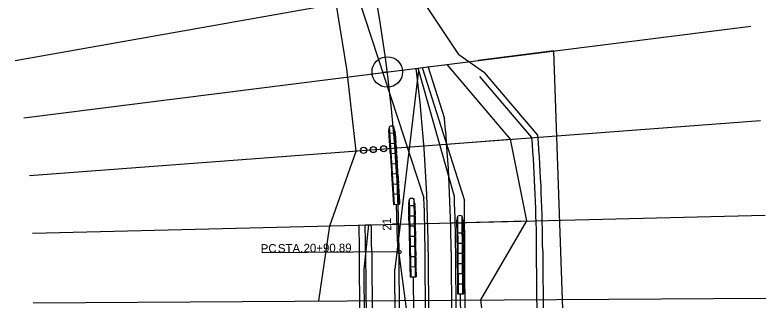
# Model space of a CAD drawing. Extents: x 2283072 to 2287933, y 586198 to 587702.
# Drawn here: x 2284307.3 to 2284553.2, y 587262.4 to 587356.1 of the extents above; entities that cross this region are included whole.
import ezdxf

# ---------------------------------------------------------------- set-up
doc = ezdxf.new("R2010")
doc.units = 0
for name, color, linetype in [('_CIVIL_CONSTRUCTION', 7, 'Continuous'), ('DR_X_Ditch', 7, 'Continuous'), ('DR_X_Headwall', 7, 'Continuous'), ('DT_X_Island', 7, 'Continuous'), ('DT_X_Terrain_Boundary', 7, 'Continuous'), ('DT_X_Void', 7, 'Continuous'), ('PV_X_EOP', 7, 'Continuous'), ('RD_P_Fence', 7, 'Continuous'), ('RS_Raster1', 7, 'Continuous'), ('RW_P_Esmt_TMP', 7, 'Continuous'), ('SV_X_Control_Cells_Found', 7, 'Continuous'), ('SV_X_Random_Point', 7, 'Continuous'), ('SV_X_Toe_of_Slope', 7, 'Continuous')]:
    doc.layers.add(name, color=color, linetype=linetype)

msp = doc.modelspace()

# ---------------------------------------------------------------- linework, layer by layer
at = {"layer": '_CIVIL_CONSTRUCTION'}
for p, q in [((2284396.97, 587431.38), (2284441.17, 587296.19)), ((2284451.16, 587296.6), (2284439.34, 587338.71)), ((2284431.58, 587294.07), (2284429.95, 587319.51)), ((2284431.28, 587319.6), (2284432.91, 587294.16)), ((2284431.71, 587318.07), (2284431.37, 587319.55)), ((2284429.72, 587317.94), (2284429.87, 587319.45)), ((2284429.75, 587317.51), (2284429.72, 587317.94)), ((2284429.92, 587317.35), (2284429.75, 587317.51)), ((2284429.77, 587317.17), (2284429.92, 587317.35)), ((2284429.96, 587314.18), (2284429.77, 587317.17)), ((2284429.92, 587317.35), (2284431.59, 587317.46)), ((2284431.59, 587317.46), (2284431.74, 587317.63)), ((2284431.76, 587317.3), (2284431.59, 587317.46)), ((2284431.71, 587318.07), (2284431.74, 587317.63)), ((2284431.76, 587317.3), (2284431.96, 587314.31)), ((2284430.14, 587314.02), (2284429.96, 587314.18)), ((2284429.98, 587313.85), (2284430.14, 587314.02)), ((2284430.17, 587310.85), (2284429.98, 587313.85)), ((2284430.14, 587314.02), (2284431.8, 587314.13)), ((2284431.8, 587314.13), (2284431.96, 587314.31)), ((2284431.98, 587313.97), (2284431.8, 587314.13)), ((2284431.98, 587313.97), (2284432.17, 587310.98)), ((2284430.35, 587310.7), (2284430.17, 587310.85)), ((2284430.19, 587310.52), (2284430.35, 587310.7)), ((2284430.19, 587310.52), (2284430.39, 587307.53)), ((2284430.35, 587310.7), (2284432.01, 587310.8)), ((2284432.01, 587310.8), (2284432.17, 587310.98)), ((2284432.19, 587310.65), (2284432.01, 587310.8)), ((2284432.19, 587310.65), (2284432.38, 587307.65)), ((2284430.56, 587307.37), (2284430.39, 587307.53)), ((2284430.41, 587307.19), (2284430.56, 587307.37)), ((2284430.56, 587307.37), (2284432.23, 587307.48)), ((2284432.23, 587307.48), (2284432.38, 587307.65)), ((2284432.4, 587307.32), (2284432.23, 587307.48)), ((2284432.4, 587307.32), (2284432.59, 587304.33)), ((2284430.41, 587307.19), (2284430.6, 587304.2)), ((2284430.78, 587304.04), (2284430.6, 587304.2)), ((2284430.62, 587303.87), (2284430.78, 587304.04)), ((2284430.62, 587303.87), (2284430.81, 587300.87)), ((2284430.78, 587304.04), (2284432.44, 587304.15)), ((2284432.44, 587304.15), (2284432.59, 587304.33)), ((2284432.62, 587303.99), (2284432.44, 587304.15)), ((2284432.62, 587303.99), (2284432.81, 587301)), ((2284430.99, 587300.72), (2284430.81, 587300.87)), ((2284430.83, 587300.54), (2284430.99, 587300.72)), ((2284430.83, 587300.54), (2284431.02, 587297.55)), ((2284430.99, 587300.72), (2284432.65, 587300.82)), ((2284432.65, 587300.82), (2284432.81, 587301)), ((2284432.83, 587300.67), (2284432.65, 587300.82)), ((2284432.83, 587300.67), (2284433.02, 587297.67)), ((2284431.2, 587297.39), (2284431.02, 587297.55)), ((2284431.05, 587297.21), (2284431.2, 587297.39)), ((2284431.2, 587297.39), (2284432.86, 587297.5)), ((2284432.86, 587297.5), (2284433.02, 587297.67)), ((2284433.04, 587297.34), (2284432.86, 587297.5)), ((2284431.05, 587297.21), (2284431.25, 587294.05)), ((2284433.04, 587297.34), (2284433.24, 587294.18)), ((2284431.25, 587294.05), (2284433.24, 587294.18)), ((2284432.57, 587282.12), (2284432.25, 587294.12)), ((2284452, 587288.65), (2284452.24, 587290.16)), ((2284452.52, 587264.72), (2284452.32, 587290.21)), ((2284453.65, 587290.22), (2284453.85, 587264.73)), ((2284454, 587288.67), (2284453.74, 587290.17)), ((2284452, 587288.22), (2284452, 587288.65)), ((2284452.17, 587288.05), (2284452, 587288.22)), ((2284452, 587287.88), (2284452.17, 587288.05)), ((2284452.03, 587284.88), (2284452, 587287.88)), ((2284452.17, 587288.05), (2284453.84, 587288.07)), ((2284453.84, 587288.07), (2284454, 587288.23)), ((2284454, 587287.9), (2284453.84, 587288.07)), ((2284454, 587288.67), (2284454, 587288.23)), ((2284454, 587287.9), (2284454.03, 587284.9)), ((2284452.2, 587284.72), (2284452.03, 587284.88)), ((2284452.03, 587284.55), (2284452.2, 587284.72)), ((2284452.05, 587281.55), (2284452.03, 587284.55)), ((2284452.2, 587284.72), (2284453.86, 587284.73)), ((2284453.86, 587284.73), (2284454.03, 587284.9)), ((2284454.03, 587284.57), (2284453.86, 587284.73)), ((2284454.03, 587284.57), (2284454.05, 587281.57)), ((2284440.46, 587222.64), (2284432.57, 587282.12)), ((2284452.22, 587281.39), (2284452.05, 587281.55)), ((2284452.06, 587281.22), (2284452.22, 587281.39)), ((2284452.06, 587281.22), (2284452.08, 587278.22)), ((2284452.22, 587281.39), (2284453.89, 587281.4)), ((2284453.89, 587281.4), (2284454.05, 587281.57)), ((2284454.06, 587281.23), (2284453.89, 587281.4)), ((2284454.06, 587281.23), (2284454.08, 587278.23)), ((2284442.67, 587114.69), (2284441.59, 587278.56)), ((2284452.67, 587114.75), (2284451.59, 587278.62)), ((2284452.25, 587278.05), (2284452.08, 587278.22)), ((2284452.08, 587277.88), (2284452.25, 587278.05)), ((2284452.08, 587277.88), (2284452.11, 587274.88)), ((2284452.25, 587278.05), (2284453.91, 587278.07)), ((2284453.91, 587278.07), (2284454.08, 587278.23)), ((2284454.08, 587277.9), (2284453.91, 587278.07)), ((2284454.08, 587277.9), (2284454.11, 587274.9)), ((2284452.27, 587274.72), (2284452.11, 587274.88)), ((2284452.11, 587274.55), (2284452.27, 587274.72)), ((2284452.11, 587274.55), (2284452.13, 587271.55)), ((2284452.27, 587274.72), (2284453.94, 587274.73)), ((2284453.94, 587274.73), (2284454.11, 587274.9)), ((2284454.11, 587274.57), (2284453.94, 587274.73)), ((2284454.11, 587274.57), (2284454.13, 587271.57)), ((2284452.3, 587271.39), (2284452.13, 587271.55)), ((2284452.13, 587271.22), (2284452.3, 587271.39)), ((2284452.13, 587271.22), (2284452.16, 587268.22)), ((2284452.3, 587271.39), (2284453.97, 587271.4)), ((2284453.97, 587271.4), (2284454.13, 587271.57)), ((2284454.13, 587271.23), (2284453.97, 587271.4)), ((2284454.13, 587271.23), (2284454.16, 587268.23)), ((2284452.33, 587268.05), (2284452.16, 587268.22)), ((2284452.16, 587267.89), (2284452.33, 587268.05)), ((2284452.16, 587267.89), (2284452.18, 587264.72)), ((2284452.33, 587268.05), (2284453.99, 587268.07)), ((2284453.99, 587268.07), (2284454.16, 587268.23)), ((2284454.16, 587267.9), (2284453.99, 587268.07)), ((2284454.16, 587267.9), (2284454.18, 587264.73)), ((2284452.18, 587264.72), (2284454.18, 587264.73)), ((2284453.97, 587144.73), (2284453.18, 587264.73))]:
    msp.add_line(p, q, dxfattribs=at)
for centre in [(2284421.41, 587311.78), (2284424.58, 587312.02), (2284428.04, 587312.28)]:
    msp.add_circle(centre, 1, dxfattribs=at)
for centre, radius, start, end in [((2284430.69, 587318.4), 1.34, 59.4868, 127.8382), ((2283936.53, 587275.24), 505.07, 0.3751, 2.3772), ((2283936.53, 587275.24), 515.07, 0.3751, 2.3772), ((2284453, 587289.06), 1.34, 56.2698, 124.6212)]:
    msp.add_arc(centre, radius, start, end, dxfattribs=at)
at = {"layer": 'DR_X_Ditch'}
for p, q in [((2284439.41, 587337.99), (2284431.63, 587272.79)), ((2284436.21, 587294.26), (2284436.43, 587295.76)), ((2284436.98, 587270.33), (2284436.51, 587295.81)), ((2284437.84, 587295.84), (2284438.31, 587270.35)), ((2284438.21, 587294.29), (2284437.93, 587295.79)), ((2284436.22, 587293.82), (2284436.21, 587294.26)), ((2284436.38, 587293.66), (2284436.22, 587293.82)), ((2284436.22, 587293.49), (2284436.38, 587293.66)), ((2284436.28, 587290.49), (2284436.22, 587293.49)), ((2284436.38, 587293.66), (2284438.05, 587293.69)), ((2284438.05, 587293.69), (2284438.21, 587293.86)), ((2284438.22, 587293.52), (2284438.05, 587293.69)), ((2284438.21, 587294.29), (2284438.21, 587293.86)), ((2284438.22, 587293.52), (2284438.28, 587290.52)), ((2284436.45, 587290.32), (2284436.28, 587290.49)), ((2284436.28, 587290.15), (2284436.45, 587290.32)), ((2284436.34, 587287.15), (2284436.28, 587290.15)), ((2284436.45, 587290.32), (2284438.11, 587290.35)), ((2284438.11, 587290.35), (2284438.28, 587290.52)), ((2284438.28, 587290.19), (2284438.11, 587290.35)), ((2284438.28, 587290.19), (2284438.34, 587287.19)), ((2284421.63, 587272.73), (2284423.19, 587287.35)), ((2284436.51, 587286.99), (2284436.34, 587287.15)), ((2284436.34, 587286.82), (2284436.51, 587286.99)), ((2284436.34, 587286.82), (2284436.4, 587283.82)), ((2284436.51, 587286.99), (2284438.17, 587287.02)), ((2284438.17, 587287.02), (2284438.34, 587287.19)), ((2284438.34, 587286.86), (2284438.17, 587287.02)), ((2284438.34, 587286.86), (2284438.4, 587283.86)), ((2284436.57, 587283.66), (2284436.4, 587283.82)), ((2284436.41, 587283.49), (2284436.57, 587283.66)), ((2284436.41, 587283.49), (2284436.46, 587280.49)), ((2284436.57, 587283.66), (2284438.24, 587283.69)), ((2284438.24, 587283.69), (2284438.4, 587283.86)), ((2284438.41, 587283.53), (2284438.24, 587283.69)), ((2284438.41, 587283.53), (2284438.46, 587280.53)), ((2284436.63, 587280.33), (2284436.46, 587280.49)), ((2284436.47, 587280.16), (2284436.63, 587280.33)), ((2284436.63, 587280.33), (2284438.3, 587280.36)), ((2284438.3, 587280.36), (2284438.46, 587280.53)), ((2284438.47, 587280.19), (2284438.3, 587280.36)), ((2284438.47, 587280.19), (2284438.52, 587277.19)), ((2284436.47, 587280.16), (2284436.52, 587277.16)), ((2284436.69, 587276.99), (2284436.52, 587277.16)), ((2284436.53, 587276.82), (2284436.69, 587276.99)), ((2284436.53, 587276.82), (2284436.58, 587273.82)), ((2284436.69, 587276.99), (2284438.36, 587277.02)), ((2284438.36, 587277.02), (2284438.52, 587277.19)), ((2284438.53, 587276.86), (2284438.36, 587277.02)), ((2284438.53, 587276.86), (2284438.58, 587273.86)), ((2284432.66, 587115.11), (2284431.63, 587272.79)), ((2284436.75, 587273.66), (2284436.58, 587273.82)), ((2284436.59, 587273.49), (2284436.75, 587273.66)), ((2284436.59, 587273.49), (2284436.65, 587270.32)), ((2284436.75, 587273.66), (2284438.42, 587273.69)), ((2284438.42, 587273.69), (2284438.58, 587273.86)), ((2284438.59, 587273.53), (2284438.42, 587273.69)), ((2284438.59, 587273.53), (2284438.65, 587270.36)), ((2284422.66, 587115.04), (2284421.63, 587272.73)), ((2284436.65, 587270.32), (2284438.65, 587270.36)), ((2284437.65, 587270.34), (2284437.73, 587258.34))]:
    msp.add_line(p, q, dxfattribs=at)
msp.add_arc((2284437.2, 587294.67), 1.34, 56.8793, 125.2306, dxfattribs=at)
at = {"layer": 'DR_X_Headwall'}
for p, q in [((2284478.52, 587316.75), (2284461.01, 587337.21)), ((2284480.09, 587278.8), (2284480.55, 587209.72))]:
    msp.add_line(p, q, dxfattribs=at)
for points in [[(2284452.62, 587343.14), (2284438.66, 587364.23), (2284432.78, 587392.55), (2284425.53, 587418.61), (2284415.47, 587450.54), (2284398.85, 587491.12)], [(2284419, 587311.53), (2284415.92, 587338.46), (2284412.32, 587360.68), (2284404.38, 587395.77), (2284395.03, 587427.62), (2284381.53, 587465.88), (2284381.59, 587465.9), (2284375.45, 587481.07)], [(2284452.62, 587343.14), (2284461.01, 587337.21), (2284461.01, 587337.21)], [(2284406.73, 587262.42), (2284410.35, 587287.03), (2284419, 587311.53)]]:
    msp.add_lwpolyline(points, dxfattribs=at)
for centre, radius, start, end in [((2283936.53, 587275.24), 543.57, 0.3751, 4.3794), ((2284433.09, 587278.49), 47, 0.37507254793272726, 0.375076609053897)]:
    msp.add_arc(centre, radius, start, end, dxfattribs=at)
at = {"layer": 'DT_X_Island'}
for p, q in [((2284421.95, 587287.32), (2284423.95, 587287.37)), ((2284422.09, 587278.42), (2284423.34, 587087.53)), ((2284424.09, 587278.43), (2284424.49, 587217.54))]:
    msp.add_line(p, q, dxfattribs=at)
for radius in [485.57, 487.57]:
    msp.add_arc((2283936.53, 587275.24), radius, 0.3751, 1.4258, dxfattribs=at)
at = {"layer": 'DT_X_Terrain_Boundary'}
for p, q in [((2284438.62, 587338.62), (2284440.6, 587338.87)), ((2284440.6, 587338.87), (2284454.48, 587295.32)), ((2284455.67, 587114.77), (2284454.48, 587295.32)), ((2284442.59, 587278.55), (2284443.94, 587072.96))]:
    msp.add_line(p, q, dxfattribs=at)
for centre, radius, start, end in [((2283936.53, 587275.24), 506.07, 0.3751, 7.195), ((2284433.09, 587278.49), 9.5, 0.3750725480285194, 0.3750766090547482)]:
    msp.add_arc(centre, radius, start, end, dxfattribs=at)
at = {"layer": 'DT_X_Void'}
for p, q in [((2284307.29, 587341.14), (2284543.59, 587383.15)), ((2284310.14, 587322.4), (2284548.25, 587352.46)), ((2284312.04, 587303.54), (2284551.36, 587321.58)), ((2284312.99, 587284.61), (2284552.91, 587290.58)), ((2284313.2, 587261.81), (2284553.2, 587263.38))]:
    msp.add_line(p, q, dxfattribs=at)
at = {"layer": 'PV_X_EOP'}
msp.add_line((2284433.09, 587278.49), (2284388.1, 587278.19), dxfattribs=at)
msp.add_circle((2284433.09, 587278.49), 0.6, dxfattribs=at)
at = {"layer": 'RD_P_Fence'}
for p, q in [((2284476.57, 587315.94), (2284459.49, 587335.91)), ((2284476.57, 587315.94), (2284476.57, 587315.94)), ((2284478.54, 587209.79), (2284478.09, 587278.78))]:
    msp.add_line(p, q, dxfattribs=at)
msp.add_circle((2284429.19, 587337.43), 5, dxfattribs=at)
for centre, radius, start, end in [((2283936.53, 587275.24), 541.57, 0.3751, 4.3104), ((2284433.09, 587278.49), 45, 0.3750725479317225, 0.37507660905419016)]:
    msp.add_arc(centre, radius, start, end, dxfattribs=at)
at = {"layer": 'RS_Raster1'}
for p, q in [((2284429.19, 587337.43), (2284428, 587337.28)), ((2284432.95, 587287.59), (2284430.95, 587287.54))]:
    msp.add_line(p, q, dxfattribs=at)
at = {"layer": 'RW_P_Esmt_TMP'}
for p, q in [((2284483.76, 587344.32), (2284458.96, 587341.19)), ((2284488.56, 587207.05), (2284483.76, 587344.32))]:
    msp.add_line(p, q, dxfattribs=at)
at = {"layer": 'SV_X_Control_Cells_Found'}
for p, q in [((2284419.96, 587287.27), (2284421.95, 587287.32)), ((2284421.34, 587087.51), (2284420.09, 587278.4))]:
    msp.add_line(p, q, dxfattribs=at)
msp.add_arc((2283936.53, 587275.24), 483.57, 0.3751, 1.4258, dxfattribs=at)
at = {"layer": 'SV_X_Random_Point'}
msp.add_line((2284434.44, 587072.89), (2284433.09, 587278.49), dxfattribs=at)
msp.add_line((2284434.44, 587072.89), (2284433.09, 587278.49), dxfattribs=at)
msp.add_arc((2283936.53, 587275.24), 496.57, 0.3751, 22.0167, dxfattribs=at)
msp.add_arc((2283936.53, 587275.24), 496.57, 0.3751, 22.0167, dxfattribs=at)
at = {"layer": 'SV_X_Toe_of_Slope'}
for p, q in [((2284442.44, 587339.35), (2284447.95, 587322.18)), ((2284442.52, 587339.11), (2284448.81, 587339.91)), ((2284448.65, 587313.84), (2284469.52, 587315.41)), ((2284449.95, 587288.02), (2284474.94, 587288.64)), ((2284450.09, 587278.6), (2284451.5, 587063.67)), ((2284450.2, 587262.71), (2284459.81, 587262.77))]:
    msp.add_line(p, q, dxfattribs=at)
msp.add_lwpolyline([(2284462.89, 587237.79), (2284459.81, 587262.77), (2284459.81, 587262.77), (2284474.94, 587288.64), (2284469.52, 587315.41), (2284448.81, 587339.91)], dxfattribs=at)
for centre, radius, start, end in [((2283936.53, 587275.24), 513.57, 0.3751, 5.2448), ((2284433.09, 587278.49), 17, 0.37507254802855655, 0.37507660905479)]:
    msp.add_arc(centre, radius, start, end, dxfattribs=at)

# ---------------------------------------------------------------- texts
at = {"layer": 'PV_X_EOP'}
for s, p in [('PC', (2284387.75, 587278.23)), (' STA. ', (2284392.33, 587278.26)), ('20+90.89', (2284401.79, 587278.33))]:
    msp.add_text(s, height=2.8, rotation=0.3751, dxfattribs=at).set_placement(p)
at = {"layer": 'RS_Raster1'}
msp.add_text('21', height=2.8, rotation=91.4258, dxfattribs=at).set_placement((2284430.5, 587285.5))

doc.saveas('drawing.dxf')
